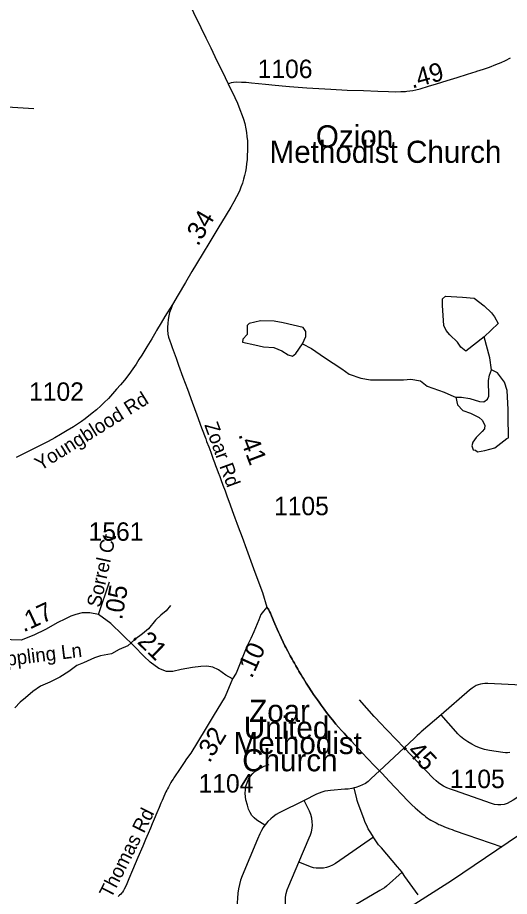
# Model space of a CAD drawing. Extents: x 1383679 to 1536984, y 460658 to 651027.
# Drawn here: x 1398965 to 1402301, y 485981 to 491939 of the extents above; entities that cross this region are included whole.
import ezdxf

# ---------------------------------------------------------------- set-up
doc = ezdxf.new("R2010")
doc.units = 0
for name, color, linetype in [('Exist Boundary Political StateLine', 7, 'Continuous'), ('Exist Cultural Church Label', 7, 'Continuous'), ('Exist Hydrographic Misc Water Feature', 7, 'Continuous'), ('Exist Road Non-System Type 51', 7, 'Continuous'), ('Exist Road Secondary Mileage Hundredths English Label', 7, 'Continuous'), ('Exist Road Secondary Type 51 Attributed', 7, 'Continuous'), ('Exist Road Secondary Type 51 Label', 7, 'Continuous'), ('Exist Road Secondary Type 51 Number Label', 7, 'Continuous')]:
    doc.layers.add(name, color=color, linetype=linetype)

msp = doc.modelspace()

# ---------------------------------------------------------------- linework, layer by layer
at = {"layer": 'Exist Boundary Political StateLine'}
msp.add_lwpolyline([(1406702.3, 489298.3), (1405745.5, 488656.5), (1405027.9, 488177.5), (1404146.2, 487594), (1403396, 487087.8), (1402797.9, 486682.3), (1402368.2, 486397.4), (1401907.9, 486087.1), (1401634.6, 485911.6)], dxfattribs=at)
at = {"layer": 'Exist Hydrographic Misc Water Feature'}
for points in [[(1399074.5, 491319.6), (1398894.5, 491331.4), (1398784.5, 491330.4), (1398728.1, 491313.5), (1398693.4, 491275.6), (1398648.4, 491226.4), (1398587.3, 491177.6), (1398539.9, 491115.4), (1398460.3, 491040.6), (1398409.7, 491007.2), (1398304.3, 490947.8), (1398227.7, 490918.9), (1398167.3, 490896.4), (1398096.9, 490878.1), (1398036.5, 490862.9)], [(1402129.3, 489774.5), (1402005.4, 489676.9), (1401971.9, 489705.5), (1401948.6, 489739.6), (1401897.4, 489789), (1401872.1, 489817.4), (1401856.7, 489851.4), (1401847.3, 489986.2), (1401846.2, 490032.2), (1401866.6, 490051.5), (1401982.5, 490043.4), (1402060.4, 490036.1), (1402129.4, 489984.6), (1402178.5, 489937.7), (1402200, 489909.4), (1402225.1, 489866.1), (1402129.3, 489774.5)], [(1400898.2, 489727.1), (1400919.3, 489776.7), (1400919.9, 489811.2), (1400900.6, 489837.8), (1400765.1, 489870.1), (1400705.3, 489881.1), (1400611.3, 489883), (1400534.8, 489864.9), (1400522.6, 489851.2), (1400521.4, 489791.3), (1400492.7, 489759.9), (1400490.2, 489737.7), (1400573.9, 489720.5), (1400631.7, 489707), (1400701.6, 489701.5), (1400757.2, 489680.7), (1400800.6, 489653.6), (1400830.4, 489643.1), (1400850.8, 489662.4), (1400898.2, 489727.1)], [(1402179, 489551.2), (1402168.6, 489631.8), (1402129.3, 489774.5)], [(1400898.2, 489727.1), (1400957.6, 489696.4), (1401046.3, 489634.6), (1401164.9, 489557.6), (1401214.1, 489520.5), (1401293.6, 489495.1), (1401357.4, 489484), (1401441.4, 489482.3), (1401581.4, 489482.8), (1401631.6, 489488.3), (1401697.4, 489476.3), (1401742.6, 489440.2)], [(1401937.2, 489365.7), (1401975.2, 489364.9), (1402033.1, 489356.3), (1402096.8, 489337), (1402126.7, 489333.9), (1402151.1, 489351.5), (1402161.5, 489371.8), (1402157.5, 489479.4), (1402166.2, 489515.3), (1402179, 489551.2)], [(1402291.8, 489281.4), (1402284.2, 489411.2), (1402267.3, 489467.3), (1402220.6, 489530.6), (1402179, 489551.2)], [(1401742.6, 489440.2), (1401857.9, 489399.2), (1401923.3, 489370), (1401937.2, 489365.7)], [(1401937.2, 489365.7), (1401948.2, 489313.7), (1401985.5, 489275.2), (1402037.3, 489257.8), (1402094.6, 489227.1), (1402116.3, 489210.2), (1402133.6, 489176.2), (1402131.1, 489150.1), (1402116.7, 489132.3), (1402075.9, 489091.3), (1402053.4, 489061.3), (1402044.9, 489036), (1402054.4, 489009.6), (1402070.3, 489005.2), (1402084, 488995.1), (1402134.3, 489003.9), (1402202.6, 489022.2), (1402281.9, 489085.5), (1402294, 489090.9), (1402290.9, 489237.1), (1402291.8, 489281.4)], [(1400002.9, 487952.9), (1399972.2, 487917.4), (1399935.6, 487888.6), (1399900.9, 487854.8), (1399851.6, 487795.9), (1399810.9, 487760.6), (1399760.1, 487722.3), (1399713.1, 487678.9), (1399652.6, 487653.8), (1399602, 487625.3), (1399527.6, 487612.9), (1399487.3, 487597.3), (1399412.6, 487565.2), (1399366.3, 487546.4), (1399311.3, 487504.8), (1399250.5, 487466.6), (1399183.9, 487433.5), (1399119.2, 487405.3), (1399068.4, 487370.2), (1399017.5, 487326.9), (1398982.9, 487298), (1398946, 487258.6)]]:
    msp.add_lwpolyline(points, dxfattribs=at)
at = {"layer": 'Exist Road Non-System Type 51'}
msp.add_line((1401586.5, 486988.3), (1401419.9, 486831.2), dxfattribs=at)
for points in [[(1401419.9, 486831.2), (1401388.5, 486863.6), (1401336.8, 486917.4), (1401276.6, 486982.2), (1401228.9, 487032.7), (1401203.4, 487060.9), (1401179.5, 487087), (1401162.5, 487106.2), (1401142.1, 487128.5), (1401124.2, 487148.9), (1401099.5, 487177.9), (1401086.1, 487194.8), (1401069.8, 487215.5), (1401060.1, 487228.4), (1401043.6, 487250.5), (1401024, 487277.8), (1401009.4, 487297.9), (1400997.9, 487313), (1400985.1, 487330.8), (1400971.4, 487350.6), (1400960.4, 487367.3), (1400936.1, 487405.2), (1400921.9, 487427.2), (1400912.6, 487441.8), (1400903.4, 487457.2), (1400896.8, 487468.1), (1400887.1, 487483.9), (1400879.4, 487496.6), (1400872.5, 487508.2), (1400864.6, 487521.5), (1400851.8, 487543.8), (1400841.8, 487561.2), (1400833.4, 487575.9), (1400825.9, 487589.1), (1400813, 487612.9), (1400803.8, 487630.3), (1400796.8, 487643), (1400784.4, 487668.1), (1400778.2, 487680.2), (1400766.8, 487704.1), (1400752, 487734.5), (1400742.5, 487754.8), (1400735.1, 487771.3), (1400725.1, 487793.6), (1400710.4, 487828.5), (1400703.2, 487845), (1400694.1, 487867.1), (1400687.5, 487882.2), (1400679.5, 487900.2), (1400674.4, 487912.2), (1400666.5, 487932.2)], [(1402474.4, 487407.8), (1402153.6, 487423.2), (1402133.9, 487423.2), (1402118.4, 487422.2), (1402103.9, 487420.1), (1402088.4, 487416), (1402074, 487409.8), (1402061.6, 487402.6), (1402047.1, 487392.2), (1402030.6, 487378.8), (1401838.5, 487212.8)], [(1401586.5, 486988.3), (1401417.4, 487164.6), (1401397.9, 487185.1), (1401383.5, 487200.5), (1401284.1, 487314.2)], [(1401838.5, 487212.8), (1401702.9, 487095.6), (1401689.5, 487084.2), (1401675, 487071.8), (1401656.4, 487054.2), (1401586.5, 486988.3)], [(1402302.4, 486955.8), (1402287.6, 486953.9), (1402273, 486953.9), (1402256.5, 486955.8), (1402164.8, 486970.4), (1402130.9, 486977.8), (1402098.6, 486987.8), (1402071.1, 486998.8), (1402044.6, 487012.6), (1402018.9, 487028.2), (1401992.4, 487046.5), (1401969.4, 487065.3), (1401951, 487082.8), (1401936.4, 487098.3), (1401838.5, 487212.8)], [(1402588.2, 486851.3), (1402577.4, 486842.3), (1402559.9, 486825.9), (1402494.4, 486756.2), (1402480, 486739.9), (1402464.6, 486726.6), (1402447.1, 486713.2), (1402326.2, 486633.3), (1402305.8, 486621), (1402285.2, 486610.8), (1402263.8, 486604.6), (1402243.2, 486601.6), (1402221.8, 486601.6), (1402200.2, 486604.6), (1402178.8, 486610.8), (1401927.6, 486697.8), (1401900, 486707.1), (1401875.4, 486717.3), (1401853.9, 486727.6), (1401835.4, 486738.8), (1401819, 486751.2), (1401802.6, 486765.5), (1401784.1, 486782.9), (1401586.5, 486988.3)], [(1400641.4, 486463.2), (1400586.6, 486498.5), (1400569.1, 486513.4), (1400554.1, 486529.7), (1400541.9, 486550), (1400531.1, 486573), (1400523, 486598.8), (1400512.1, 486636.7), (1400509.4, 486657), (1400508.1, 486681.3), (1400509.4, 486704.4), (1400513.5, 486727.4), (1400521.6, 486751.8), (1400531.1, 486774.8), (1400544.6, 486795.2), (1400560.9, 486814.1), (1400579.9, 486831.7), (1400598.9, 486843.9), (1400617.9, 486853.4), (1400638.1, 486862.8), (1400672, 486875.1)], [(1401419.9, 486831.2), (1401363.9, 486779.3), (1401343.2, 486760.8), (1401323.6, 486747.3), (1401304, 486737), (1401283.4, 486727.7), (1401259.6, 486719.4), (1401247.4, 486716.1)], [(1401247.4, 486716.1), (1401232.6, 486712.2), (1401205.9, 486708), (1401183.1, 486707), (1401088, 486699.8), (1401068.4, 486697.7), (1401047.6, 486693.6), (1401029.1, 486688.4), (1401010.5, 486681.2), (1400992.9, 486673.9), (1400907.9, 486631.4)], [(1401378.8, 486381.5), (1401359.9, 486411.8), (1401343.1, 486440), (1401332.6, 486461.9), (1401323.2, 486482.8), (1401314.9, 486501.7), (1401272, 486616.7), (1401267.9, 486630.2), (1401264.6, 486642.8), (1401247.4, 486716.1)], [(1400907.9, 486631.4), (1400738.6, 486546.8), (1400719, 486535.4), (1400698.4, 486520.9), (1400681.9, 486506.5), (1400662.1, 486487.9), (1400643.6, 486466.2), (1400641.4, 486463.2)], [(1400872.4, 486213.6), (1400941.9, 486377.7), (1400950.6, 486398.5), (1400957.4, 486419.3), (1400962.8, 486442.4), (1400963.9, 486464.3), (1400962.8, 486487.4), (1400959.5, 486511.6), (1400952.9, 486535.8), (1400944.1, 486559.8), (1400907.9, 486631.4)], [(1400641.4, 486463.2), (1400630.1, 486447.6), (1400618.8, 486426.9), (1400607.4, 486404.2), (1400591.9, 486368), (1400487.5, 486119.9), (1400477.1, 486091), (1400468.9, 486062.1), (1400462.6, 486033.2), (1400458.6, 486003.2), (1400455.5, 485968), (1400454.4, 485937), (1400455.5, 485902.9), (1400459.6, 485870.8), (1400467.9, 485836.8), (1400479.2, 485800.6), (1400496.9, 485758.2), (1400502.4, 485747.7)], [(1401378.8, 486381.5), (1401120.1, 486202.9), (1401101.6, 486193.1), (1401079.6, 486184.3), (1401058.9, 486177.8), (1401040.4, 486173.4), (1401022.9, 486171.2), (1401004.4, 486171.2), (1400989, 486172.3), (1400972.6, 486175.6), (1400957.4, 486180), (1400872.4, 486213.6)], [(1401572.4, 486144.4), (1401557.4, 486162.9), (1401541.8, 486181.7), (1401433, 486309.2), (1401413.1, 486331.2), (1401398.5, 486351.1), (1401380.8, 486378.2), (1401378.8, 486381.5)], [(1400917.4, 485689.3), (1400810.1, 485848.4), (1400799.1, 485867.1), (1400791.5, 485886.8), (1400786, 485908.8), (1400782.8, 485930.8), (1400781.6, 485952.8), (1400782.8, 485975.8), (1400786, 485999.9), (1400792.6, 486025.2), (1400803.6, 486051.6), (1400872.4, 486213.6)], [(1401572.4, 486144.4), (1401466.8, 486050.4), (1401452.4, 486039.5), (1401438.1, 486030.7), (1401421.6, 486020.8), (1401103.4, 485833.1), (1401091.2, 485825.4), (1401079.1, 485817.7), (1401061.6, 485803.4), (1400917.4, 485689.3)], [(1401680.9, 485991.4), (1401592, 486116.8), (1401575.2, 486140.9), (1401572.4, 486144.4)]]:
    msp.add_lwpolyline(points, dxfattribs=at)
at = {"layer": 'Exist Road Secondary Type 51 Attributed'}
msp.add_line((1399513, 487891), (1399587.4, 488113.1), dxfattribs=at)
for points in [[(1399484.7, 493346.9), (1399492, 493337.9), (1399500.4, 493325.5), (1399509.1, 493311.2), (1399526, 493279.3), (1399546.1, 493238.4), (1399574.4, 493181.3), (1399615.5, 493098.6), (1399631.9, 493066), (1399658.1, 493013.7), (1399715.5, 492896.2), (1399761, 492800.6), (1399824.3, 492670.8), (1399896, 492521.5), (1399964.7, 492378.4), (1400051.7, 492196.8), (1400104.7, 492086.7), (1400158.7, 491974), (1400207.3, 491872.7), (1400241.4, 491802.5), (1400274.3, 491733.3), (1400315.7, 491646.9), (1400351.2, 491575), (1400393.3, 491489.6)], [(1400393.3, 491489.6), (1400415.3, 491498.9), (1400428.7, 491501.9), (1400450.3, 491502.5), (1400483.8, 491502.1), (1400514.3, 491501), (1400551, 491497.6), (1400599.6, 491493.2), (1400646.3, 491488.5), (1400711, 491481.6), (1400783.6, 491474.1), (1400808.6, 491471.5), (1400925.8, 491462.5), (1401089.2, 491453.6), (1401200.7, 491448.2), (1401311.3, 491443.7), (1401408.5, 491439.6), (1401480, 491437.1), (1401528.6, 491436.3), (1401564.7, 491437.1), (1401596.6, 491438.9), (1401605.7, 491439.8), (1401624.5, 491441.6), (1401645.6, 491445.1), (1401665.9, 491449), (1401696.1, 491456.3), (1401752.2, 491473.8), (1401805.7, 491489.8), (1401877.9, 491512.2), (1401945.2, 491533.3), (1402016.9, 491556.1), (1402075, 491574.5), (1402080.3, 491576.2), (1402123.8, 491590), (1402164.7, 491604.1), (1402207.8, 491620.6), (1402245, 491635.7), (1402273.1, 491648.7), (1402306.7, 491665.9)], [(1400393.3, 491489.6), (1400439.1, 491396.7), (1400455.9, 491358), (1400472.9, 491316.9), (1400487.7, 491276.3), (1400496.3, 491250.2), (1400504.9, 491220.7), (1400513, 491183.9), (1400517.3, 491159.1), (1400520.4, 491133.8), (1400523.1, 491103.9), (1400524.6, 491070.3), (1400524, 491038.8), (1400522.6, 491003.3), (1400520.8, 490975.6), (1400518.2, 490950), (1400514.8, 490921.6), (1400510.4, 490896.4), (1400504.3, 490869), (1400497.9, 490843.7), (1400489.6, 490817), (1400479.6, 490788.4), (1400472, 490769.9), (1400462.1, 490748.5), (1400449.2, 490722.8), (1400431.3, 490689.5), (1400410.2, 490652.9), (1400380.3, 490602.7), (1400322.9, 490508.1), (1400268.2, 490418.2), (1400216.5, 490333.2), (1400146.5, 490216.7), (1400103.5, 490143.8), (1400054.4, 490058.8), (1400014.9, 489993.5)], [(1400014.9, 489993.5), (1399964.4, 489911.9), (1399938.1, 489869.7), (1399907.7, 489818.1), (1399901.7, 489807.9), (1399874.4, 489762), (1399841.2, 489706.1), (1399807.4, 489650.7), (1399787.7, 489620.1), (1399768.2, 489590.1), (1399747.1, 489558.4), (1399718.3, 489518.8), (1399689.1, 489481.3), (1399663.1, 489449.3), (1399636.5, 489419.2), (1399609.2, 489388), (1399580.6, 489357.4), (1399551.8, 489329), (1399529, 489307.2), (1399499.1, 489280.8), (1399470.5, 489256.2), (1399423, 489219.3), (1399398.7, 489201.4), (1399378, 489187.5), (1399343.9, 489165.3), (1399301.7, 489139.8), (1399255.4, 489112.4), (1399216.4, 489090.8), (1399171.5, 489066), (1398977.3, 488968.7), (1398954.6, 488957.6)], [(1400014.9, 489993.5), (1400005.6, 489967.9), (1399996, 489940.6), (1399990.6, 489916.1), (1399986.6, 489892.3), (1399983.3, 489864.2), (1399981.1, 489839.6), (1399981.3, 489817.6), (1399983.3, 489798.1), (1399984.6, 489792), (1399989, 489772), (1399997, 489747.1), (1400003.5, 489729.4), (1400013, 489701.9), (1400025.9, 489666.6), (1400039.2, 489630.3), (1400056.6, 489583.1), (1400086.6, 489501.2), (1400116.8, 489419.7), (1400149.1, 489331), (1400180.4, 489246.3), (1400213.2, 489158.7), (1400241.1, 489082.2), (1400247.1, 489066), (1400260.8, 489029.4), (1400274.7, 488992.3), (1400284.8, 488964.6), (1400291.6, 488945.5), (1400300.5, 488921.6), (1400307.5, 488902.8), (1400316, 488879.7), (1400325.7, 488854.2), (1400335.7, 488828.2), (1400343.1, 488808), (1400356.9, 488770), (1400371.5, 488731.1), (1400379.6, 488709.7), (1400387.3, 488689.4), (1400398.4, 488659.6), (1400407.2, 488635.7), (1400421.2, 488597.8), (1400439.2, 488548.4), (1400451.8, 488512.4), (1400461.4, 488485.8), (1400487.3, 488415.6), (1400517, 488334.6), (1400564.8, 488204.2), (1400594.6, 488124.4), (1400625.8, 488040.3), (1400655.9, 487942.5)], [(1399513, 487891), (1399455.4, 487904.4), (1399403, 487904.4), (1399359.7, 487893), (1399325.6, 487881.6), (1399285.3, 487859.5), (1399236.8, 487838.3), (1399154.8, 487790.5), (1399075.5, 487752.2), (1398988.6, 487717.6), (1398920.3, 487719.9), (1398861.8, 487726.3), (1398817.8, 487733.5), (1398776.8, 487742.7), (1398729, 487765.4), (1398692.6, 487776.8)], [(1400422.8, 487455.1), (1400377.5, 487480.7), (1400327.4, 487517.1), (1400289.4, 487535.7), (1400247.5, 487542.5), (1400206.8, 487539.9), (1400150.9, 487533.9), (1400074.2, 487519), (1400017.8, 487505.7), (1399974.5, 487505.7), (1399922.6, 487525.3), (1399863.3, 487568.8), (1399821.4, 487609.4), (1399754.4, 487678.5), (1399598.1, 487831.5), (1399513, 487891)], [(1400655.9, 487942.5), (1400632.2, 487915.4), (1400614, 487892.4), (1400600.1, 487855.8), (1400566.6, 487774.6), (1400545.6, 487729.9), (1400520.5, 487674.4), (1400446.6, 487494.3), (1400422.8, 487455.1)], [(1400655.9, 487942.5), (1400679.5, 487900.3), (1400687.5, 487882.2), (1400694.1, 487867.1), (1400703.3, 487845), (1400710.3, 487828.5), (1400725.2, 487793.6), (1400735.2, 487771.3), (1400742.5, 487754.8), (1400752, 487734.5), (1400766.7, 487704), (1400778.2, 487680.2), (1400784.4, 487668.1), (1400796.8, 487643), (1400803.7, 487630.3), (1400813, 487612.9), (1400825.9, 487589.1), (1400833.4, 487575.9), (1400841.8, 487561.2), (1400851.7, 487543.9), (1400864.7, 487521.5), (1400872.5, 487508.2), (1400879.4, 487496.6), (1400887.1, 487483.9), (1400896.8, 487468.1), (1400903.3, 487457.3), (1400912.6, 487441.8), (1400921.9, 487427.2), (1400936.1, 487405.2), (1400960.4, 487367.4), (1400971.4, 487350.6), (1400985.1, 487330.8), (1400997.9, 487313), (1401009.3, 487298), (1401024.1, 487277.7), (1401043.6, 487250.5), (1401060.2, 487228.4), (1401069.7, 487215.5), (1401086.1, 487194.7), (1401099.6, 487177.9), (1401124.2, 487148.9), (1401142.1, 487128.5), (1401162.5, 487106.2), (1401179.5, 487087), (1401203.4, 487060.9), (1401228.8, 487032.7), (1401276.7, 486982.3), (1401336.8, 486917.4), (1401388.5, 486863.6), (1401437.3, 486813.3), (1401485.4, 486761.7), (1401526.3, 486718.4), (1401573.1, 486669.4), (1401609.8, 486631.6), (1401638.9, 486602), (1401661.3, 486580.8), (1401677.3, 486567), (1401693.5, 486553.4), (1401709.8, 486540), (1401721.8, 486531.2), (1401732.1, 486523), (1401743.7, 486514.5), (1401756.8, 486505.6), (1401767.6, 486498.7), (1401780.8, 486491), (1401790, 486485.6), (1401803.1, 486478.6), (1401814.3, 486472.8), (1401822.4, 486469), (1401829.8, 486465.9), (1401839.8, 486461.6), (1401846.7, 486458.6), (1401860.2, 486453.2), (1401878.6, 486446.1), (1401896.1, 486439.7), (1401911.6, 486433.9), (1401926.2, 486428.5), (1402011.5, 486397.8), (1402248.6, 486316.8)], [(1400422.8, 487455.1), (1400372.6, 487337.3), (1400290.3, 487203.2), (1400235.9, 487112.5), (1400139, 486952.7), (1400111.5, 486913.4), (1400095.1, 486888.7), (1400068.1, 486849), (1400053.4, 486828.2), (1400038.6, 486806), (1400024.7, 486784.7), (1400019.2, 486775.9), (1400011.4, 486763.9), (1400005.2, 486752.4), (1399998.2, 486739.9), (1399988.5, 486722.5), (1399982.3, 486710.8), (1399976.7, 486701.1), (1399970.9, 486689.1), (1399964, 486673.3), (1399957, 486658.3), (1399952.4, 486647.5), (1399945.5, 486631.6), (1399936.6, 486612), (1399924.2, 486583.8), (1399908.8, 486546.8), (1399891.4, 486505.1), (1399878.3, 486472.7), (1399866, 486443), (1399850.9, 486406.8), (1399833.4, 486365.6), (1399813.9, 486321.6), (1399781.1, 486245.6), (1399744.7, 486158.7), (1399719.3, 486099), (1399704.7, 486065), (1399695.8, 486045.2), (1399688.5, 486030.2), (1399682.4, 486019.9), (1399676.1, 486010.1), (1399671.5, 486004.7), (1399664.2, 485996.2), (1399656.5, 485988.5), (1399646.1, 485979.5)]]:
    msp.add_lwpolyline(points, dxfattribs=at)

# ---------------------------------------------------------------- texts
at = {"layer": 'Exist Cultural Church Label'}
for s, p in [('Ozion ', (1400987.8, 491058.9)), ('Methodist Church', (1400674, 490954.2)), ('Zoar ', (1400535.3, 487164)), ('United', (1400499.2, 487050)), ('Methodist', (1400429.9, 486945.9)), ('Church', (1400488.2, 486829.1))]:
    msp.add_text(s, height=150, dxfattribs=at).set_placement(p)
at = {"layer": 'Exist Road Secondary Mileage Hundredths English Label'}
for s, rotation, p in [('.49', 15.45822, (1401640.9, 491457.4)), ('.34', 59.6487, (1400188.3, 490384.2)), ('.41', 290.75628, (1400460.3, 489111.8)), ('.05', 79.82547, (1399672.8, 487851.7)), ('.17', 25.0985, (1399005.7, 487770)), ('.21', 315.61034, (1399737.7, 487734.4)), ('.10', 65.65371, (1400553.3, 487453.8)), ('.32', 58.76841, (1400265.9, 486880.3)), ('.45', 313.38509, (1401569.4, 486992.7))]:
    msp.add_text(s, height=125, rotation=rotation, dxfattribs=at).set_placement(p)
at = {"layer": 'Exist Road Secondary Type 51 Label'}
for s, rotation, p in [('Youngblood Rd', 31.99854, (1399119.1, 488863.6)), ('Zoar Rd', 290.15219, (1400230.1, 489177.7)), ('Sorrel Ct', 77.61723, (1399525.9, 487935.1)), ('Appling Ln', 6.88856, (1398809.7, 487533.1)), ('Thomas Rd', 63.18348, (1399598.6, 485962.9))]:
    msp.add_text(s, height=95, rotation=rotation, dxfattribs=at).set_placement(p)
at = {"layer": 'Exist Road Secondary Type 51 Number Label'}
for s, p in [('1106', (1400593, 491528.9)), ('1102', (1399042.6, 489340.8)), ('1105', (1400704, 488565.3)), ('1561', (1399446.2, 488391.9)), ('1105', (1401896.7, 486714.9)), ('1104', (1400192.1, 486684.7))]:
    msp.add_text(s, height=125, dxfattribs=at).set_placement(p)

doc.saveas('drawing.dxf')
